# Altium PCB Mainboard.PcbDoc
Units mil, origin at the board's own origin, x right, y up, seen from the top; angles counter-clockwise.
Board outline 3816.81 x 2675.98 mil, 2 copper layers (Top Layer, Bottom Layer); 40 components, 44 nets, 262 pads, 14 vias.
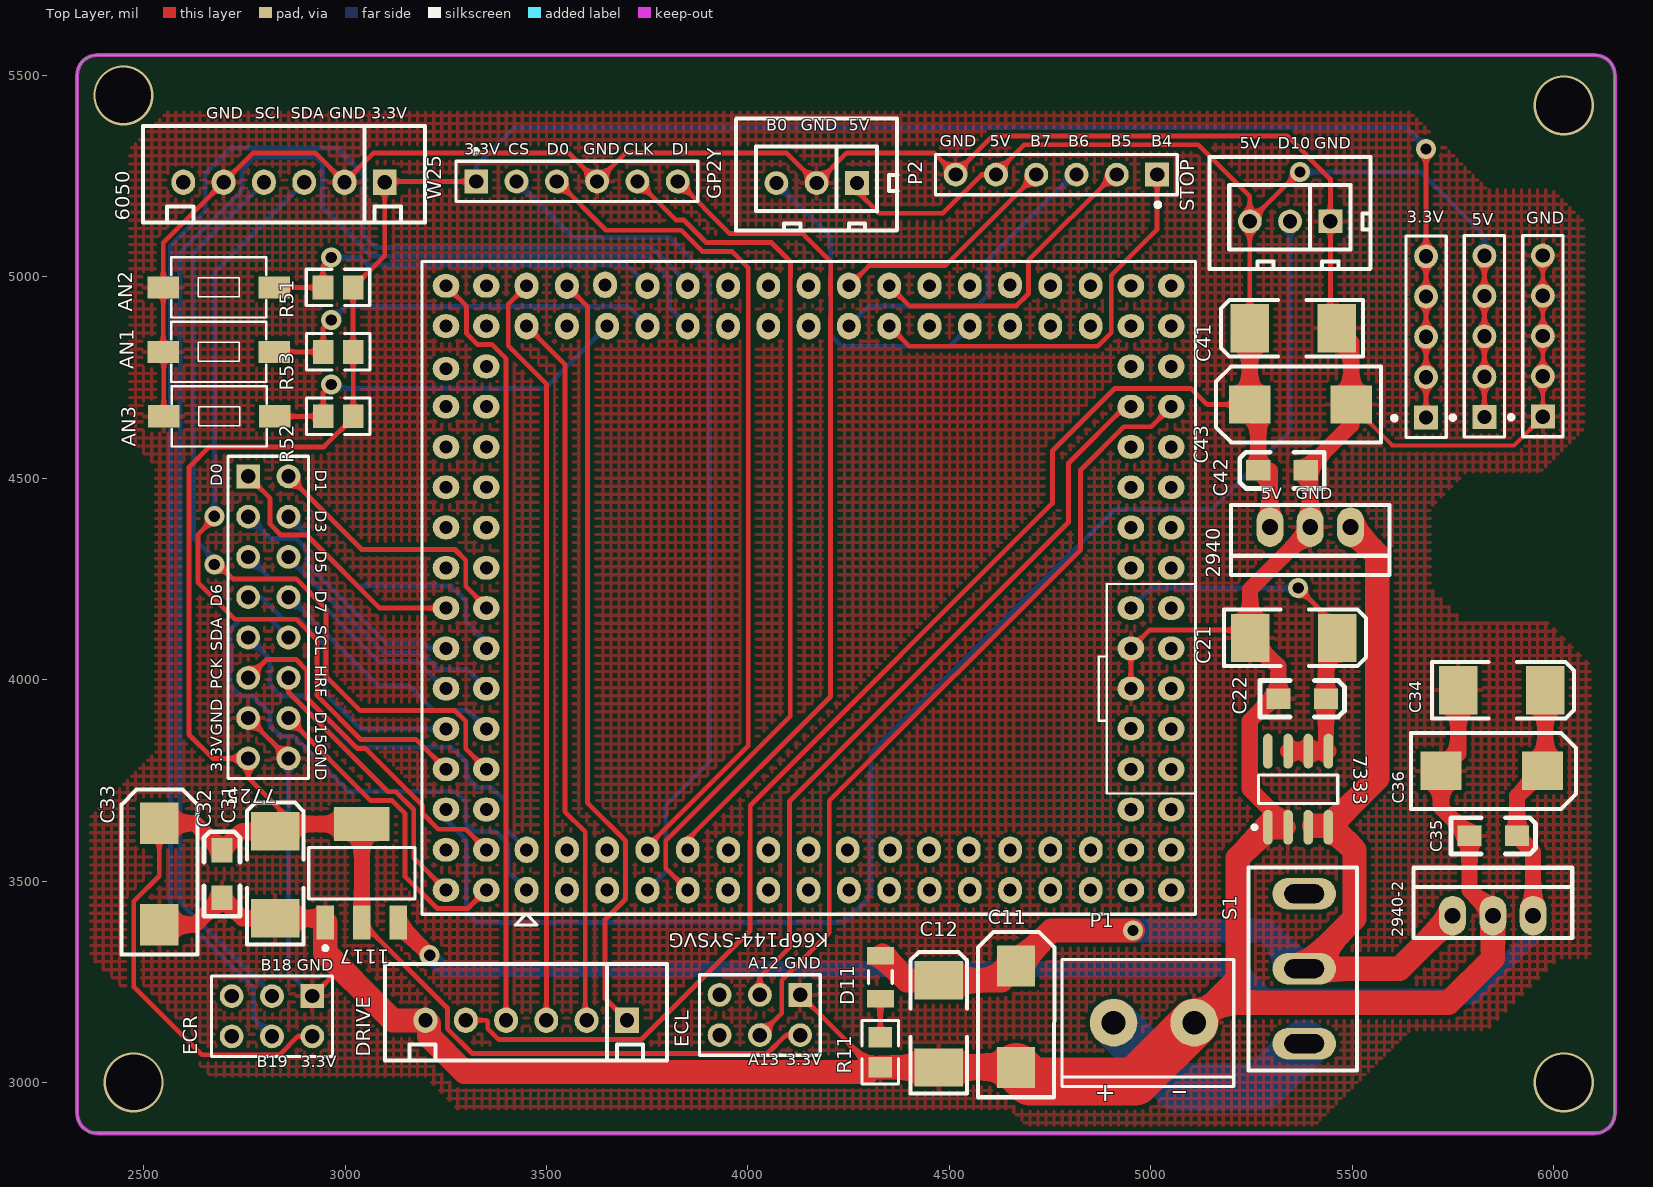
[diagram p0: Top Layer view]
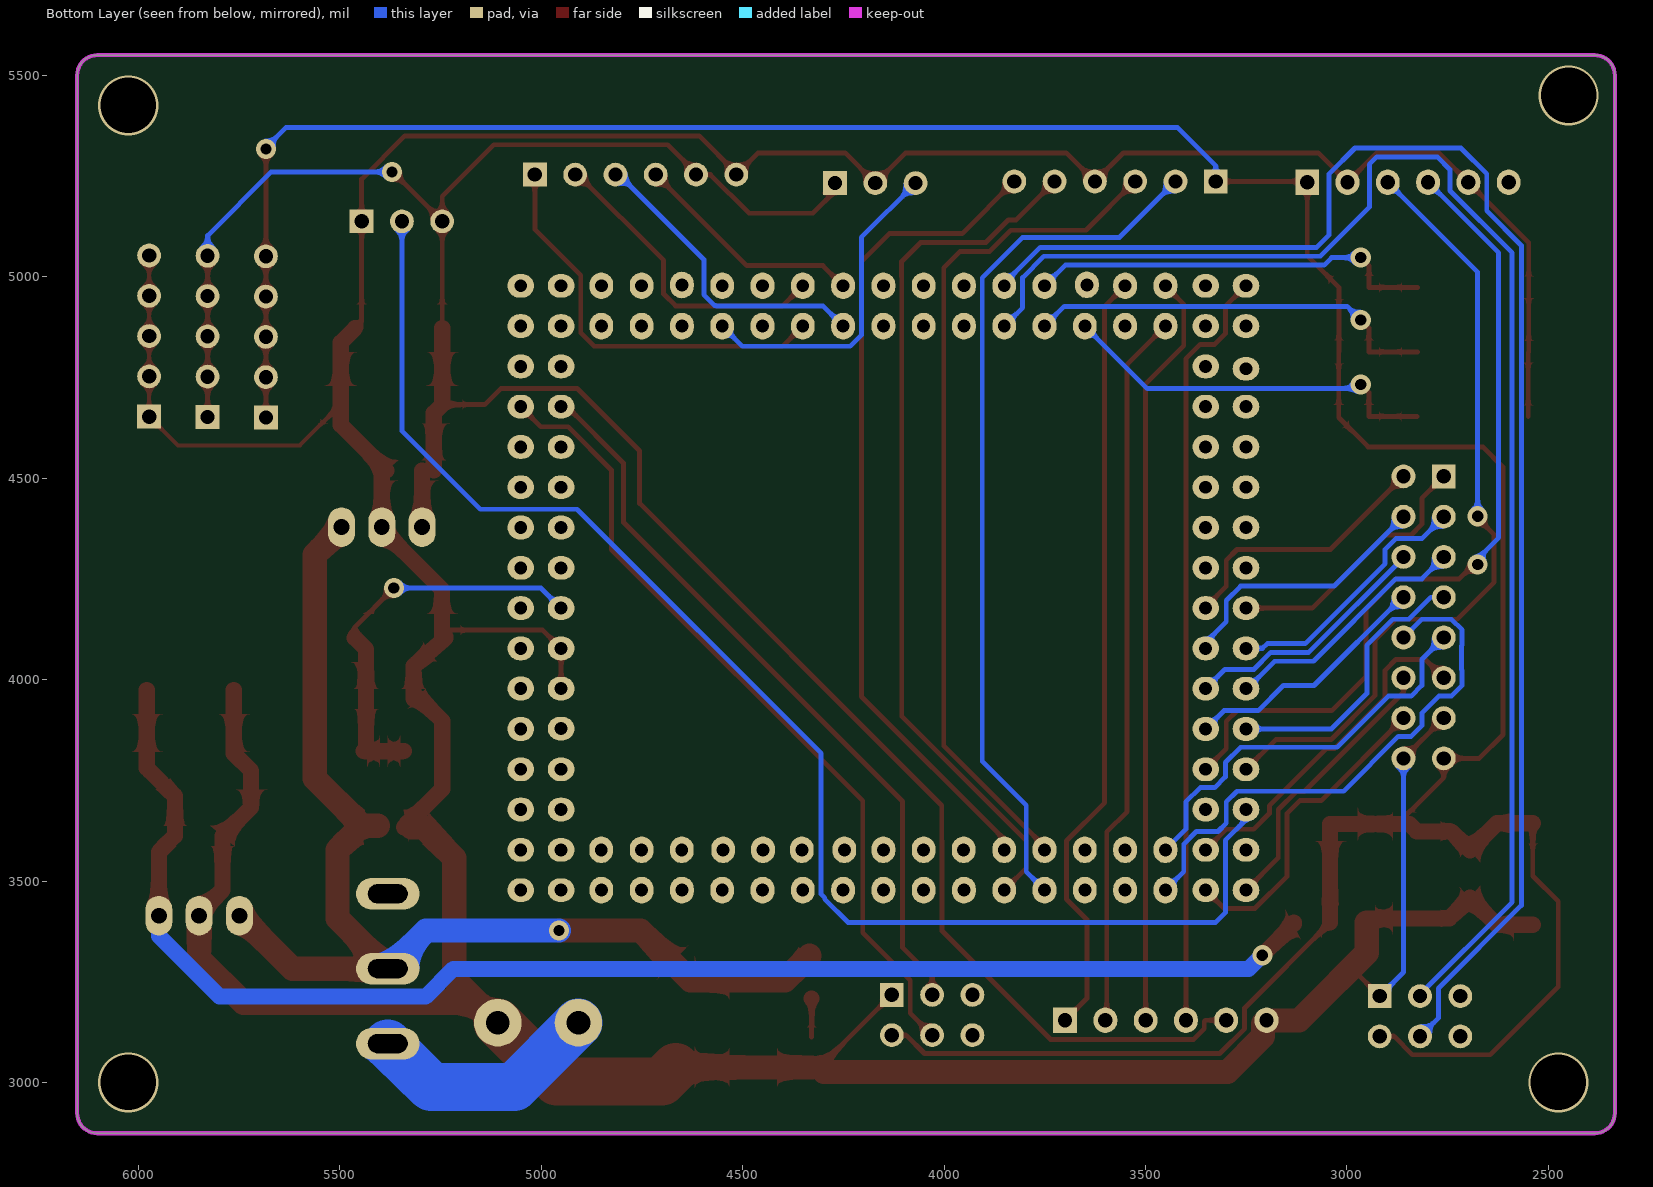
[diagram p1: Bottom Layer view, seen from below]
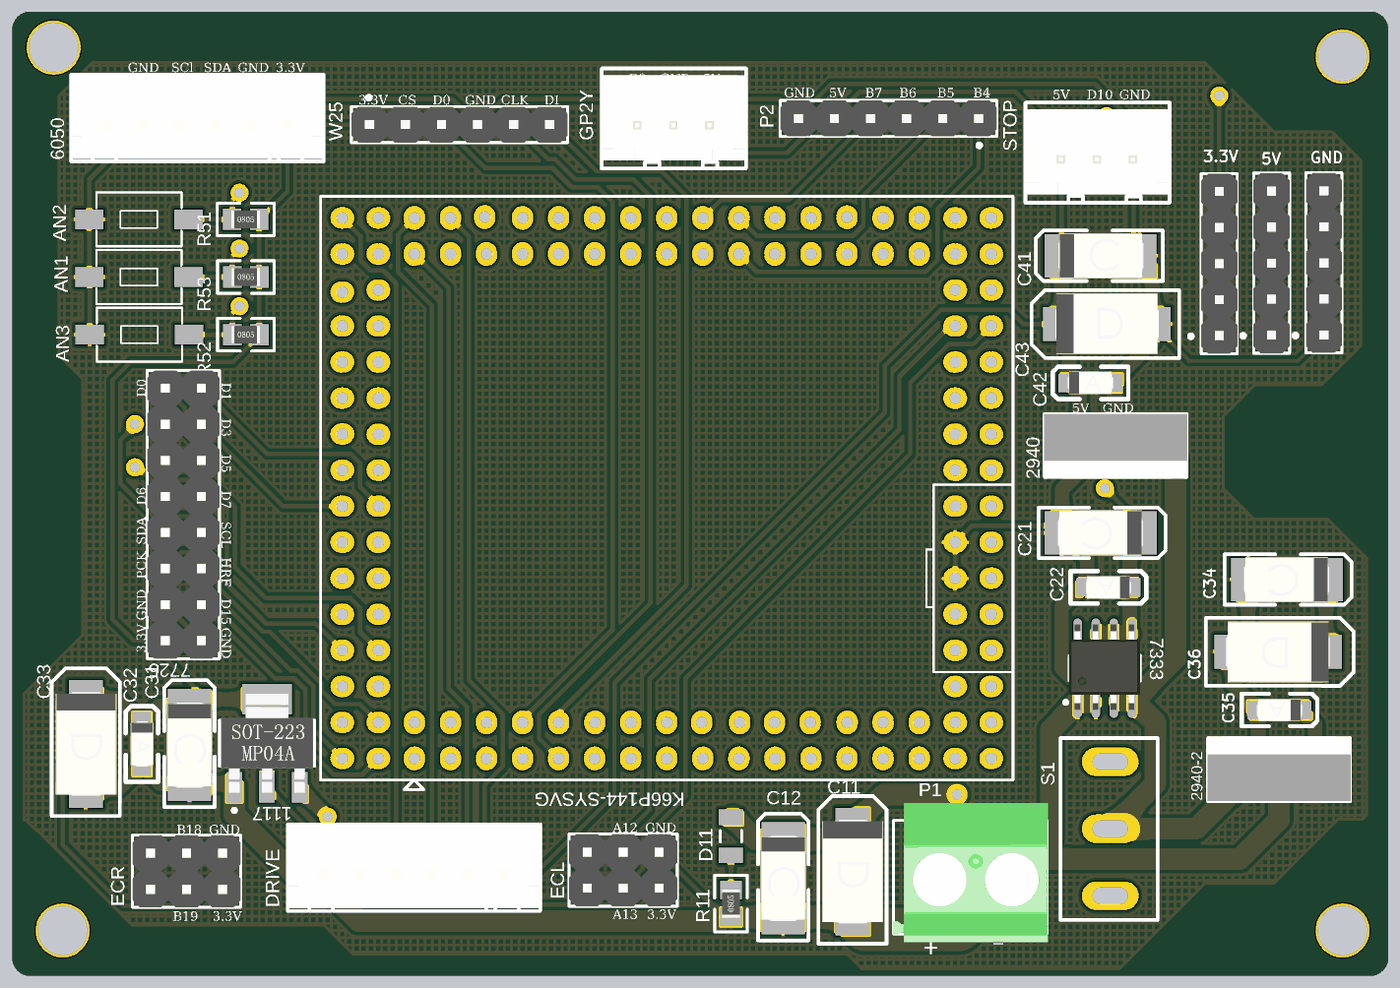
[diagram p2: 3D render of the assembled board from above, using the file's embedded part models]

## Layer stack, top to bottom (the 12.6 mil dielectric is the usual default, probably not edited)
Top Solder: solder mask 0.4, Solder Resist, Dk 3.5
Top Layer: signal copper 1.4
Dielectric 1: dielectric 12.6, FR-4, Dk 4.8
Bottom Layer: signal copper 1.4
Bottom Solder: solder mask 0.4, Solder Resist, Dk 3.5

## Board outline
2385,2874.02 cw(c2385,2924.02) 2335,2924.02 2335,5500 cw(c2385,5500) 2385,5550 6101.81,5550 cw(c6101.81,5500) 6151.81,5500 6151.81,2924.02 cw(c6101.81,2924.02) 6101.81,2874.02

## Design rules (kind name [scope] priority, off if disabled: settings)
Clearance [All] p1: gap=10 ignorepadtopadclearanceinfootprint=FALSE except(0: Arc-Hole Track-Hole SMDPad-Hole THPad-Hole Via-Hole Fill-Hole Poly-Hole Region-Hole Text-Hole)
Height [All] p1: minheight=0 maxheight=2000 prefheight=500
HoleSize [All] p1: absolutevalues=TRUE maxlimit=157.48 minlimit=1 maxpercent=80.000 minpercent=20.000
PolygonConnect [All] p1: connectstyle=Relief reliefconductorwidth=10 reliefentries=4 polygonreliefangle="90 Angle" airgapwidth=10
RoutingVias [All] p1: holewidth=28 width=50 viastyle="Through Hole" minholewidth=28 minwidth=50 maxholewidth=28 maxwidth=50
SilkToSilkClearance [All] p1: silktosilkclearance=0
SilkToSolderMaskClearance [IsPad] p1: minsilkscreentomaskgap=0 clearancetoexposedcopper=TRUE
SolderMaskExpansion [All] p1: expansion=4
Width [All] p1: maxlimit=150 minlimit=10 preferedwidth=12 minimp=50.000000 maximp=50.000000 favimp=50.000000
26 further rules are at their usual default settings.

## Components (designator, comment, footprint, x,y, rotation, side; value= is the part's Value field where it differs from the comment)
3.3V "Header 5" HDR1X5 5683.14,4650.68 r90 top
5V "Header 5" HDR1X5 5828,4652 r90 top
1117 "17" SOT-223 3041.63,3519.44 r0 top
2940 "40-1" TO-220B 5395.63,4378.44 r180 top
2940-2 "LM2940" TO-220B 5849,3414 r0 top
6050 "Header 6" HX2.54-6 3098.63,5234.44 r180 top
7333 "7333" SO8_N 5365.63,3727.95 r90 top
7725 "Header 8X2" HDR2X8 2759.63,4504.44 r270 top
AN1 "Button" SMT4*6*2.5 2686.63,4813.44 r0 top
AN2 "Button" SMT4*6*2.5 2686.63,4973.44 r0 top
AN3 "Button" SMT4*6*2.5 2687.83,4653.44 r0 top
C11 "Cap Pol3" C7343 4665.35,3163.35 r270 top value=100uF
C12 "Cap Pol3" C6032 4472.63,3141.44 r270 top value=10uF
C21 "Cap Pol3" C6032 5350.63,4104.44 r180 top value=10uF
C22 "Cap Pol3" C3216 5375.63,3952.44 r180 top value=0.1uF
C31 "Cap Pol3" C6032 2825.63,3511.44 r270 top value=10uF
C32 "Cap Pol3" C3216 2694.63,3517.44 r270 top value=0.1uF104
C33 "Cap Pol3" C7343 2538.63,3517.44 r270 top value=100uF
C34 "Cap Pol3" C6032 5867,3975 r180 top value=10uF
C35 "Cap Pol3" C3216 5850,3612 r180 top value=0.1uF104
C36 "Cap Pol3" C7343 5846,3774 r180 top value=100uF
C41 "Cap Pol3" C6032 5357.63,4871.44 r0 top value=10uF
C42 "Cap Pol3" C3216 5325.63,4519.44 r0 top value=0.1uF104
C43 "Cap Pol3" C7343 5371.63,4682.44 r0 top value=100uF
D11 "LED1" C1206 4328.63,3261.44 r270 top
DRIVE "Header 6" HX2.54-6 3699.63,3154.44 r180 top
ECL "Header 3X2" HDR2X3 4129.63,3217.44 r180 top
ECR "Header 3X2" HDR2X3 2918.63,3214.44 r180 top
GND "Header 5" HDR1X5 5973.1,4652.68 r90 top
GP2Y "Header 3" HX2.54-3 4270.63,5232.44 r180 top
K66P144-SYSVG "LQ_KXXP144-SYSVG" LQ_KXXP144-SYSVG 3450.63,3477.44 r0 top
P1 "Header 2" 2PIN-5.08A 5107.63,3148.44 r180 top
P2 "Header 6" HDR1X6 5015.63,5253.44 r180 top
R11 "Res3" R0805 4328.63,3074.84 r90 top
R51 "Res3" R0805 2982.63,4973.44 r0 top value=3.3K
R52 "Res3" R0805 2983.03,4653.44 r0 top value=3.3K
R53 "Res3" R0805 2983.03,4813.44 r0 top value=3.3K
S1 "S2W" SW-TO3 5380.63,3282.44 r0 top
STOP "Header 3" HX2.54-3 5445.63,5137.44 r180 top
W25 "MHDR1X6" HDR1X6 3325.63,5236.44 r0 top

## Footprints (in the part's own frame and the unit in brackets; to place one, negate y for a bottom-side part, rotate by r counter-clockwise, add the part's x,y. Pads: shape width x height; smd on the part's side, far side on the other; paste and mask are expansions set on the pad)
2PIN-5.08A [mm]
  round 3 hole 1.5: 1(0,0) 2(5.08,0)
  silkscreen extent -2.49,-3.99 8.33,4.01, body extent -2.54,-5.2 8.36,4.6, height 14.2
C1206 [mm] "Chip Capacitor, Body 3.2x1.6mm, IPC High Density"
  rect 1.1x1.7 smd: 1(-1.35,0) 2(1.35,0)
  silkscreen extent -0.4,-0.75 0.4,0.75, body extent -1.7,-0.9 1.7,0.9, height 1.3
C3216 [mil] "A型/1206"
  rect 60x51.18 smd: 1(-59,0) 2(59,0)
  silkscreen extent -105,-45 105,45, body extent -63,-31 63,32, height 63
C6032 [mil] "C型"
  rect 95x120 smd: 1(-112,1) 2(104,1)
  silkscreen extent -183,-69 169,71, body extent -121,-62 115,64, height 102
C7343 [mm] "D型"
  rect 2.6x2.4 smd: 1(-3.202,0.007) 2(3.198,0.007)
  silkscreen extent -5.33,-2.39 5.08,2.41, body extent -3.65,-2.12 3.65,2.18, height 2.9
HDR1X5 [mm] "Connector; Header; 5 Position"
  rect 1.5x1.5 hole 0.9: 1(0,0)
  round 1.5 hole 0.9: 2(2.54,0) 3(5.08,0) 4(7.62,0) 5(10.16,0)
  silkscreen extent -1.27,-1.27 11.43,2.14, body extent -1.27,-1.27 11.43,1.27, height 8.54
HDR1X6 [mm] "Connector; Header; 6 Position"
  rect 1.5x1.5 hole 0.9: 1(0,0)
  round 1.5 hole 0.9: 2(2.54,0) 3(5.08,0) 4(7.62,0) 5(10.16,0) 6(12.7,0)
  silkscreen extent -1.27,-1.27 13.97,2.04, body extent -1.27,-1.27 13.97,1.27, height 8.54
HDR2X3 [mm] "Connector; Header; 3x2 Position"
  rect 1.5x1.5 hole 0.9: 1(0,0)
  round 1.5 hole 0.9: 2(0,2.54) 3(2.54,0) 4(2.54,2.54) 5(5.08,0) 6(5.08,2.54)
  silkscreen extent -1.27,-1.27 6.35,3.81, body extent -1.27,-1.27 6.35,3.81, height 8.54
HDR2X8 [mm] "Connector; Header; 8x2 Position"
  rect 1.5x1.5 hole 0.9: 1(0,0)
  round 1.5 hole 0.9: 2(0,2.54) 3(2.54,0) 4(2.54,2.54) 5(5.08,0) 6(5.08,2.54) 7(7.62,0) 8(7.62,2.54) 9(10.16,0) 10(10.16,2.54) 11(12.7,0) 12(12.7,2.54) 13(15.24,0) 14(15.24,2.54) 15(17.78,0) 16(17.78,2.54)
  silkscreen extent -1.27,-1.27 19.05,3.81, body extent -1.27,-1.27 19.05,3.81, height 8.54
HX2.54-3 [mm]
  rect 1.5x1.5 hole 0.9: 1(0,0)
  round 1.5 hole 0.9: 2(2.54,0) 3(5.08,0)
  silkscreen extent -2.54,-4.06 7.63,3, body extent -2.41,-3.58 7.59,2.42, height 7
HX2.54-6 [mm]
  rect 1.5x1.6 hole 0.9: 1(0,0)
  oval 1.5x1.6 hole 0.9: 2(2.54,0) 3(5.08,0) 4(7.62,0) 5(10.16,0) 6(12.7,0)
  silkscreen extent -2.54,-3.56 15.24,2.54, body extent -2.54,-3.63 15.24,2.36, height 6.1
LQ_KXXP144-SYSVG [mil]
  oval 59x66 hole 32: 1(0,0) 2(0,100) 3(100,0) 4(100,100) 5(200,0) 6(200,100) 7(300,0) 8(300,100) 9(400,0) 10(400,100) 11(500,0) 12(500.79,100) 13(600,0) 14(600,100) 15(700,0) 16(700,100) 17(800,0) 18(796.85,100) 19(900,0) 20(902.36,100) 21(1000,0) 22(998.82,100) 23(1100,0) 24(1097.64,100) 25(1200,0) 26(1200.39,100) 27(1300,0) 28(1300,100) 29(1400,0) 30(1400.39,100) 63(1400,1500) 64(1400,1400) 65(1300,1500) 66(1300,1400) 67(1200,1501.97) 68(1200,1400) 69(1100,1500) 70(1100,1400) 71(1000,1500) 72(1000,1400) 73(900,1500) 74(900,1400) 75(800,1500) 76(800,1400) 77(700,1500) 78(700,1400) 79(600,1500) 80(600,1400) 81(500,1500) 82(500,1400) 83(400,1500) 84(400,1400) 85(300,1500) 86(300,1400) 87(194.88,1502.36) 88(200,1400) 89(100,1500) 90(100,1400) 91(0,1500) 92(0,1400)
  oval 66x59 hole 32: 31(1500,0) 32(1600,0) 33(1500,100) 34(1600,100) 35(1500,200) 36(1600,200) 37(1500,300) 38(1600,300) 39(1500,400.79) 40(1600,400) 41(1500,500) 42(1600,500.39) 43(1500,600) 44(1600,600) 45(1500,700) 46(1600,700) 47(1500,800) 48(1600,800) 49(1500,900) 50(1600,900) 51(1500,1000) 52(1600,1000) 53(1500,1100) 54(1600,1100) 55(1500,1200) 56(1600,1200) 57(1500,1300) 58(1600,1300) 59(1500,1400) 60(1600,1400) 61(1500,1500) 62(1600,1500) 93(-100,1500) 94(-200,1500) 95(-100,1400) 96(-200,1400) 97(-100,1300) 98(-200,1294.09) 99(-100,1200) 100(-200,1200) 101(-100,1100) 102(-200,1100) 103(-100,1000) 104(-200,1000) 105(-100,899.61) 106(-200,900.39) 107(-100,800) 108(-200,800) 109(-100,700) 110(-200,700) 111(-100,600) 112(-200,600) 113(-100,500) 114(-200,500) 115(-100,400) 116(-200,400) 117(-100,300) 118(-200,300) 119(-100,200) 120(-200,200) 121(-100,100) 122(-200,100) 123(-100,0) 124(-200,0)
  silkscreen extent -260,-87 1660,1560
R0805 [mm]
  rect 1.3x1.5 smd: 1(-0.95,0) 2(0.95,0)
  silkscreen extent -2,-1.15 2,1.15, body extent -1,-0.63 1,0.63, height 0.55
SMT4*6*2.5 [mm]
  rect 2x1.4 smd: 1(-3.5,0) 2(3.5,0)
  silkscreen extent -3,-1.9 3,1.9, body extent -2.85,-1.75 3.25,1.95, height 2.5
SO8_N [mm] "SOIC, 8-Leads, Body 4.9x3.9mm, Pitch 1.27mm, IPC Medium Density"
  oval 2.2x0.6 smd: 1(-2.4,1.905) 2(-2.4,0.635) 3(-2.4,-0.635) 4(-2.4,-1.905) 5(2.4,-1.905) 6(2.4,-0.635) 7(2.4,0.635) 8(2.4,1.905)
  silkscreen extent -2.52,-2.5 0.9,2.88, body extent -2.94,-2.48 3.1,2.54, height 1.6
SOT-223 [mm]
  rect 1.1x2.15 smd: 1(-2.3,-3.1) 2(0,-3.1) 3(2.3,-3.1)
  rect 3.5x2.15 smd: 2(0,3.1)
  silkscreen extent -3.35,-4.85 3.35,1.63, body extent -3.25,-3.48 3.25,3.48, height 1.7
SW-TO3 [mm]
  oval 4x2 hole 1.2 slot 2.5 at 0 deg: 1(0,-4.724) 2(0,0) 3(0,4.724)
  silkscreen extent -3.5,-6.43 3.33,6.39, body extent -3.43,-6.36 3.43,6.35, height 28.55
TO-220B [mm]
  oval 1.7x2.5 hole 1: 1(-2.54,0) 2(0,0) 3(2.54,0)
  silkscreen extent -5,-1.4 5,3.02, body extent -5.08,-1.4 5.08,3.18, height 18.54

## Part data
3.3V 5V GND: "Header, 5-Pin"
1117: library part AMS1117, "SOT-223"
2940: library part LM2940, "SOT-223"
2940-2: "SOT-223"
6050 DRIVE P2 W25: "Header, 6-Pin"
7725: "Header, 8-Pin, Dual row"
C11 C12 C21 C22 C31 C32 C33 C34 C35 C36 C41 C42 C43: "Polarized Capacitor (Surface Mount)"
D11: library part LED3, "Typical BLUE SiC LED"
ECL ECR: "Header, 3-Pin, Dual row"
GP2Y STOP: "Header, 3-Pin"
P1: "Header, 2-Pin"
R11 R51 R52 R53: "Resistor"
S1: library part SW-SPST, "Single-Pole, Single-Throw Switch"

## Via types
v1: diameter 50, hole 28, Top Layer to Bottom Layer, 10 vias
v2: diameter 149.61, hole 137.8, Top Layer to Bottom Layer, 4 vias

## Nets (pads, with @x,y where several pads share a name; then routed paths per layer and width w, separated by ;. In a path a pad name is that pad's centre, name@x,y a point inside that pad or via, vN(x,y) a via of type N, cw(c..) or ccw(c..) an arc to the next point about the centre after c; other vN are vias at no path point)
3.3V: 3.3V.1 3.3V.2 3.3V.3 3.3V.4 3.3V.5 1117.2 6050.1 7725.15 C31.1 C32.1 C33.1 ECL.2 ECR.2 R51.2 R52.2 R53.2 W25.1 | length 8501.5
  Top Layer w12: C33.1 2538.91,3512.59 2475.66,3449.34 2475.66,3237.41 2644.16,3068.91 2837.49,3068.91 2883.02,3114.44 ECR.2 ; C31.1@2866.63,3649.49 2759.63,3756.49 7725.15 2671.63,3804.44 2612.63,3863.44 2612.63,4527.44 2662.63,4577.44 2947.38,4577.44 3020.43,4650.5 R52.2 R53.2 3020.03,4813.84 R51.2 3098.63,5052.04 6050.1 3100.63,5236.44 W25.1 ; 1117.2@3041.63,3397.39 3254.1,3184.92 3254.1,3133.61 3315.8,3071.91 4048.49,3071.91 4094.02,3117.44 ECL.2 ; v1(5683,5317) 5683,5106.82 5683.14,5106.68 3.3V.5 3.3V.4 3.3V.3 3.3V.2 3.3V.1
  Top Layer w40: C33.1 2627.57,3643.5 C32.1 2741.63,3623.44 C31.1 2844.68,3641.49 3041.63,3641.49 1117.2@3041.63,3397.39
  Bottom Layer w12: W25.1 3325.63,5275.63 3420,5370 5634,5370 5683,5321 v1(5683,5317)
5V: 5V.1 5V.2 5V.3 5V.4 5V.5 2940.3 C41.1 C42.1 C43.1 DRIVE.5 GP2Y.1 P2.5 STOP.3 | length 6078.9
  Top Layer w12: DRIVE.5 3351.84,3154.44 3354.1,3152.18 3354.1,3133.61 3380.77,3106.94 3735.78,3106.94 4005.13,3376.29 4005.13,3599.79 4005.63,3600.29 4005.63,3687.44 4755.63,4437.44 4755.63,4567.44 4911.13,4722.94 5099.63,4722.94 5139.85,4682.72 C43.1 ; GP2Y.1@4295.63,5207.44 GP2Y.1 4270.63,5212.44 4325.63,5157.44 4484.02,5157.44 4580.02,5253.44 P2.5 4615.63,5257.44 4685.63,5327.44 5117.63,5327.44 5245.63,5199.44 STOP.3 ; C41.1 C41.1 STOP.3 ; v1(5370,5260) 5368.19,5260 STOP.3 ; 5V.1 5V.2 5V.3 5V.4 5V.5
  Top Layer w40: C41.1 C43.1 5266.63,4661.65 C42.1 ; 2940.3 C42.1@5295.63,4519.44
  Bottom Layer w12: v1(5370,5260) 5670,5260 ; 5671,5260 5670,5260 ; 5V.5 5828,5102 5670,5260
5V-2: 1117.3 2940-2.3 C34.1 C35.1 C36.1 | length 3613.3
  Top Layer w40: 1117.3 3132.18,3393.82 v1(3210,3316) ; 2940-2.3 5949,3572 C35.1 5909,3710.66 C36.1 5979,3780.66 C34.1
  Bottom Layer w40: v1(3210,3316) 3244,3282 5218,3282 5286.93,3213.07 5798.07,3213.07 5949,3364 2940-2.3
ADC1_SE8: GP2Y.3 K66P144-SYSVG.70 | length 810.7
  Bottom Layer w12: GP2Y.3 4205.13,5097.94 4205.13,4855.09 4232.78,4827.44 4500.63,4827.44 K66P144-SYSVG.70
ADC1_SE10: K66P144-SYSVG.74 P2.1 | length 1025.5
  Top Layer w12: K66P144-SYSVG.74 4400.63,4827.44 4868.48,4827.44 4901.63,4860.59 4901.63,5003.44 5015.63,5117.44 P2.1
ADC1_SE11: K66P144-SYSVG.73 P2.2 | length 769.8
  Top Layer w12: K66P144-SYSVG.73 4400.63,4927.44 4666.51,4927.44 4696.13,4957.06 4696.13,5040.79 4908.78,5253.44 P2.2
ADC1_SE12: K66P144-SYSVG.76 P2.3 | length 772.1
  Bottom Layer w12: K66P144-SYSVG.76 4300.63,4927.44 4565.63,4927.44 4566.63,4928.44 4569.48,4928.44 4596.13,4955.09 4596.13,5042.76 4806.82,5253.44 P2.3
ADC1_SE13: K66P144-SYSVG.75 P2.4 | length 579.3
  Top Layer w12: K66P144-SYSVG.75 4300.63,5027.44 4489.63,5027.44 P2.4
CLK: K66P144-SYSVG.9 W25.5 | length 2173.2
  Top Layer w12: W25.5 3821.16,5140.91 3840.04,5140.91 3896.02,5084.94 4058.13,5084.94 4105.63,5037.44 4105.63,5000.29 4105.13,4999.79 4105.13,3908.79 3796.13,3599.79 3796.13,3531.94 K66P144-SYSVG.9
CS: K66P144-SYSVG.7 W25.2 | length 2162.5
  Bottom Layer w12: W25.2 3564.63,5097.44 3805.13,5097.44 3905.13,4997.44 3905.13,3796.94 3796.13,3687.94 3796.13,3522.94 K66P144-SYSVG.7
D0: 7725.1 K66P144-SYSVG.110 | length 667.2
  Top Layer w12: 7725.1 2814.1,4449.97 2814.1,4385.58 2840.77,4358.91 2905.16,4358.91 3086.63,4177.44 K66P144-SYSVG.110 K66P144-SYSVG.110@3250.63,4180.44
D1: 7725.2 K66P144-SYSVG.109 | length 666.2
  Top Layer w12: 7725.2 3041.13,4322.94 3272.98,4322.94 3299.63,4296.29 3299.63,4231.44 3350.63,4180.44 K66P144-SYSVG.109
D2: 7725.3 K66P144-SYSVG.112 | length 647.1
  Bottom Layer w12: 7725.3 2814.1,4349.97 2878.49,4349.97 2905.16,4323.3 2905.16,4288.07 3103.78,4089.44 3197.86,4089.44 3209.86,4077.44 K66P144-SYSVG.112
D3: 7725.4 K66P144-SYSVG.111 | length 666.2
  Bottom Layer w12: 7725.4 3032.13,4231.94 3263.98,4231.94 3299.63,4196.29 3299.63,4143.44 3350.63,4092.44 K66P144-SYSVG.111
D4: 7725.5 K66P144-SYSVG.114 | length 626.4
  Bottom Layer w12: 7725.5 2814.1,4249.97 2878.49,4249.97 3083.02,4045.44 3179.63,4045.44 3247.63,3977.44 K66P144-SYSVG.114
D5: 7725.6 K66P144-SYSVG.113 | length 627.6
  Bottom Layer w12: 7725.6 2859.63,4302.48 3094.67,4067.44 3188.74,4067.44 3230.76,4025.42 3302.65,4025.42 K66P144-SYSVG.113
D6: 7725.7 K66P144-SYSVG.116 | length 696.7
  Bottom Layer w12: 7725.7 2791.63,4204.44 2846.1,4149.97 2886.1,4149.97 2950.63,4085.44 2950.63,3965.44 3038.63,3877.44 K66P144-SYSVG.116
D7: 7725.8 K66P144-SYSVG.115 | length 626.4
  Bottom Layer w12: 7725.8 2862.74,4204.44 3081.74,3985.44 3157.63,3985.44 3220.13,3922.94 3305.13,3922.94 K66P144-SYSVG.115
DI: K66P144-SYSVG.10 W25.6 | length 2069.9
  Top Layer w12: W25.6 3955.13,5106.94 4136.13,5106.94 4205.63,5037.44 4205.63,5000.29 4205.13,4999.79 4205.13,4955.09 4205.63,4954.59 4205.63,4900.29 4205.13,4899.79 4205.13,3958.05 3850.63,3603.55 K66P144-SYSVG.10
DO: K66P144-SYSVG.8 W25.3 | length 2112.2
  Top Layer w12: W25.3 3526.63,5236.44 3647.63,5115.44 3834.4,5115.44 3886.9,5062.94 3960.13,5062.94 4000.63,5022.44 4000.63,3835.4 3750.63,3585.4 K66P144-SYSVG.8
"ECL A12": ECL.3 K66P144-SYSVG.55 | length 1850.3
  Top Layer w12: ECL.3 4029.63,3261.44 4102.78,3334.59 4102.78,3697.44 4795.63,4390.29 4795.63,4537.44 4935.63,4677.44 K66P144-SYSVG.55
"ECL A13": ECL.4 K66P144-SYSVG.56 | length 2022.7
  Top Layer w12: ECL.4 4084.1,3171.91 4084.1,3253.6 4201.98,3371.47 4201.98,3698.79 4825.63,4322.44 4825.63,4520.29 4932.78,4627.44 5000.63,4627.44 K66P144-SYSVG.56
"ECR B18": ECR.3 K66P144-SYSVG.84 | length 3609.8
  Bottom Layer w12: ECR.3 2818.63,3218.88 2590,3447.51 2590,5059.46 2744.16,5213.61 2744.16,5265.97 2775.63,5297.44 2925.63,5297.44 2944.16,5278.91 2944.16,5172.56 3065.91,5050.8 3752.27,5050.8 3805.13,4997.94 3805.13,4922.94 K66P144-SYSVG.84
"ECR B19": ECR.4 K66P144-SYSVG.83 | length 3738.9
  Bottom Layer w12: ECR.4 2773.1,3159.97 2773.1,3233.3 2567,3439.4 2567,5077.51 2653.1,5163.61 2653.1,5255.27 2717.28,5319.44 2979.98,5319.44 3044.16,5255.27 3044.16,5103.67 3075.03,5072.8 3761.38,5072.8 3850.63,4983.55 K66P144-SYSVG.83
GND: 1117.1 2940-2.2 2940.2 6050.2 6050.5 7333.1 7333.2 7725.13 7725.16 AN1.1 AN2.1 AN3.1 C11.2 C12.2 C21.2 C22.2 C31.2 C32.2 C33.2 C34.2 C35.2 C36.2 C41.2 C42.2 C43.2 DRIVE.6 ECL.1 ECR.1 GND.1 GND.2 GND.3 GND.4 GND.5 GP2Y.2 K66P144-SYSVG.41 K66P144-SYSVG.43 P1.1 P2.6 R11.1 STOP.1 W25.4 | length 13029.5
  Top Layer w10: C43.2 5599.25,4581 ; 5598.25,4581 5599.25,4581 ; 5900.43,4581 5599.25,4581 ; 5901.43,4581 GND.1 GND.2 GND.3 GND.4 GND.5
  Top Layer w12: AN3.1 2550.04,4812.24 AN1.1 AN2.1 2548.83,5084.65 6050.5 2771.63,5307.44 2925.63,5307.44 6050.2 3071.63,5307.44 3554.63,5307.44 W25.4 3696.63,5307.44 4095.63,5307.44 GP2Y.2 4245.63,5307.44 4461.63,5307.44 P2.6 4515.63,5257.44 4607.63,5349.44 5338.54,5349.44 5445.63,5242.35 STOP.1 5445.63,4888.44 C41.2 ; 7725.13 7725.16 ; ECR.1 2986.63,3282.44 2990.63,3282.44 ; 1117.1 1117.1@2951.08,3412.89 ; 3052.63,3214.44 3055.63,3217.44 ; ECL.1 4309.63,3037.44 R11.1 ; K66P144-SYSVG.41 K66P144-SYSVG.43 4996.13,4122.94 5227.13,4122.94 C21.2@5237.63,4103.44
  Top Layer w40: C33.2 2627.72,3391.54 C32.2 2745.63,3407.44 C31.2 2941.03,3407.44 1117.1 ; C21.2@5237.63,4103.44 5242.67,4098.97 5316.63,4033.44 C22.2 5300.63,3952.44 5245.63,3897.44 5245.63,3728.46 7333.2 ; C21.2 5246.63,4223.94 5395.63,4372.94 2940.2 C42.2@5395.63,4501.44 ; C42.2 5497.54,4632.35 C43.2 5497.54,4836.54 C41.2 ; C34.2 5763,3816.63 C36.2 5720.09,3682.91 C35.2 5791,3477.5 5849,3419.5 2940-2.2
  Top Layer w60: 1117.1 2951.08,3321.99 2990.63,3282.44 3055.63,3217.44 3118.93,3154.15 3199.63,3154.15 3208.1,3145.67 3208.1,3114.56 3296.75,3025.91 4298.1,3025.91 R11.1@4309.63,3037.44 ; R11.1 C12.2 C11.2 ; P1.1 5157.19,3198 ; 7333.1@5290.63,3632.44 5215.63,3557.44 5215.63,3256.44 5157.19,3198 ; 7333.1 5321.65,3633.46 5325.63,3637.44 ; 2940-2.2 5849,3308 5739,3198 5157.19,3198
  Top Layer w120: C11.2 4700.63,3002.44 4961.63,3002.44 P1.1
  Bottom Layer w12: 7725.16 2859.63,3273.44 ECR.1
HRF: 7725.12 K66P144-SYSVG.124 | length 700.5
  Top Layer w12: 7725.12 2859.63,3968.83 3106.65,3721.81 3126.27,3721.81 3170.53,3677.55 3170.53,3557.54 K66P144-SYSVG.124
IIC_SCL: 6050.4 K66P144-SYSVG.117 | length 2066.2
  Top Layer w12: v1(2675.63,4285.44) 2685.63,4285.44 2721.1,4249.97 2878.49,4249.97 2952.63,4175.83 2952.63,4008.44 3038.13,3922.94 3272.98,3922.94 3299.63,3896.29 3299.63,3828.44 K66P144-SYSVG.117
  Bottom Layer w12: v1(2675.63,4285.44) 2675.63,4300.44 2623.63,4352.44 2623.63,5059.44 6050.4
IIC_SDA: 6050.3 K66P144-SYSVG.118 | length 1991.3
  Top Layer w12: v1(2675.63,4405.44) 2675.63,4400.44 2634.63,4359.44 2634.63,4241.44 2726.1,4149.97 2878.49,4149.97 2930.63,4097.83 2930.63,3960.05 3039.53,3851.15 3176.92,3851.15 K66P144-SYSVG.118
  Bottom Layer w12: v1(2675.63,4405.44) 2675.63,5011.44 6050.3
KEY1: AN1.2 K66P144-SYSVG.86 R53.1 | length 1027.9
  Top Layer w12: AN1.2 R53.1 2945.63,4872.44 v1(2965.63,4892.44)
  Bottom Layer w12: v1(2965.63,4892.44) 2999.63,4926.44 3701.63,4926.44 K66P144-SYSVG.86
KEY2: AN2.2 K66P144-SYSVG.85 R51.1 | length 1017.2
  Top Layer w12: AN2.2 R51.1 2945.23,5027.04 v1(2965.63,5047.44)
  Bottom Layer w12: v1(2965.63,5047.44) 3038.16,5047.44 3056.8,5028.8 3699.27,5028.8 K66P144-SYSVG.85
KEY3: AN3.2 K66P144-SYSVG.88 R52.1 | length 963.4
  Top Layer w12: AN3.2 R52.1 2945.63,4712.44 v1(2965.63,4732.44)
  Bottom Layer w12: v1(2965.63,4732.44) 2965.63,4728.44 2971.13,4722.94 3272.98,4722.94 3273.48,4722.44 3327.78,4722.44 3328.28,4722.94 3372.98,4722.94 3373.48,4722.44 3495.63,4722.44 K66P144-SYSVG.88
NetD11_2: D11.2 R11.2 | length 96
  Top Layer w12: R11.2 D11.2
NetP1_2: P1.2 S1.1 | length 583.6
  Bottom Layer w120: P1.2 5067.13,2988.94 5273.13,2988.94 S1.1
PCK: 7725.11 K66P144-SYSVG.121 | length 857
  Top Layer w12: 7725.11 2805.16,4049.97 2878.49,4049.97 2905.16,4023.3 2905.16,3954.41 3030.42,3829.15 3050.04,3829.15 3192.53,3686.66 3192.53,3667.7 3231.78,3628.44 3299.63,3628.44 K66P144-SYSVG.121
PWM1: DRIVE.1 K66P144-SYSVG.89 | length 1926.6
  Top Layer w12: K66P144-SYSVG.89 3601.63,4926.44 3601.63,3694.29 3696.13,3599.79 3696.13,3455.09 3645.63,3404.59 3645.63,3208.44 DRIVE.1
PWM2: DRIVE.2 K66P144-SYSVG.92 | length 1784.7
  Top Layer w12: K66P144-SYSVG.92 3545.63,4782.44 3545.63,3672.4 3596.13,3621.9 3596.13,3157.94 DRIVE.2
PWM3: DRIVE.3 K66P144-SYSVG.91 | length 1881
  Top Layer w12: K66P144-SYSVG.91 3405.13,4931.94 3405.13,4828.44 3499.63,4733.94 DRIVE.3
PWM4: DRIVE.4 K66P144-SYSVG.94 | length 1905.6
  Top Layer w12: K66P144-SYSVG.94 3301.63,4926.44 3301.63,4858.59 3328.28,4831.94 3363.98,4831.94 3399.63,4796.29 DRIVE.4
SCCBSCL: 7725.10 K66P144-SYSVG.1 | length 1351.1
  Bottom Layer w12: 7725.10 2814.1,4149.97 2740.77,4149.97 2714.1,4123.3 2714.1,4085.58 2715.63,4084.06 2715.63,4024.83 2714.1,4023.3 2714.1,3985.58 2740.77,3958.91 2772.16,3958.91 2814.1,3916.97 2814.1,3885.58 2840.77,3858.91 2872.16,3858.91 3008.13,3722.94 3272.98,3722.94 3299.63,3696.29 3299.63,3643.44 3320.13,3622.94 3374.02,3622.94 3405.13,3591.83 3405.13,3522.94 K66P144-SYSVG.1
SCCBSDA: 7725.9 K66P144-SYSVG.2 | length 1007.7
  Bottom Layer w12: 7725.9 2814.1,4049.97 2814.1,3985.58 2840.77,3958.91 2897.16,3958.91 3024.13,3831.94 3263.98,3831.94 3301.63,3794.29 3301.63,3758.59 3328.28,3731.94 3363.98,3731.94 3399.63,3696.29 3399.63,3628.44 K66P144-SYSVG.2
STOP: K66P144-SYSVG.120 STOP.2 | length 3563.1
  Bottom Layer w12: K66P144-SYSVG.120 3250.63,3652.44 3301.63,3601.44 3301.63,3421.44 3325.63,3397.44 4238.48,3397.44 4296.13,3455.09 4296.13,3458.44 4305.13,3467.44 4305.13,3816.94 4911.13,4422.94 5151.13,4422.94 5345.63,4617.44 STOP.2
VB: 2940-2.1 2940.1 7333.3 7333.4 C11.1 C12.1 D11.1 S1.2 | length 2887.6
  Top Layer w40: D11.1 D11.1@4334.02,3314.59
  Top Layer w60: D11.1@4334.02,3314.59 4395.17,3253.44 C12.1 4629.66,3253.44 C11.1 4753.66,3377.44 v1(4955.63,3377.44) ; 5405.63,3637.44 7333.4@5444.61,3637.44 ; 2940.1 5495.63,4376.44 5562,4310.07 5562,3754.83 7333.4@5444.61,3637.44 ; 2940-2.1 5617.44,3282.44 S1.2 5505.63,3407.44 5505.63,3577.44 5449.61,3633.46 7333.4 7333.4@5444.61,3637.44
  Bottom Layer w60: v1(4955.63,3377.44) 5285.63,3377.44 S1.2
VCC: 7333.5 7333.6 7333.7 C21.1 C22.1 K66P144-SYSVG.45 | length 995
  Top Layer w12: v1(5365.63,4227.44) 5462.63,4130.44 C21.1
  Top Layer w40: 7333.7 7333.6 7333.5 5434.63,3828.44 C22.1 5434.63,4075.44 C21.1
  Bottom Layer w12: K66P144-SYSVG.45 5000.63,4227.44 v1(5365.63,4227.44)
VSY: 7725.14 K66P144-SYSVG.123 | length 797.4
  Top Layer w12: 7725.14 3064.26,3699.81 3117.16,3699.81 3148.53,3668.44 3148.53,3511.7 3228.28,3431.94 3305.13,3431.94 K66P144-SYSVG.123
pads on no net: 6050.6 7333.8 ECL.5 ECL.6 ECR.5 ECR.6 K66P144-SYSVG.3 K66P144-SYSVG.4 K66P144-SYSVG.5 K66P144-SYSVG.6 K66P144-SYSVG.11 K66P144-SYSVG.12 K66P144-SYSVG.13 K66P144-SYSVG.14 K66P144-SYSVG.15 K66P144-SYSVG.16 K66P144-SYSVG.17 K66P144-SYSVG.18 K66P144-SYSVG.19 K66P144-SYSVG.20 K66P144-SYSVG.21 K66P144-SYSVG.22 K66P144-SYSVG.23 K66P144-SYSVG.24 K66P144-SYSVG.25 K66P144-SYSVG.26 K66P144-SYSVG.27 K66P144-SYSVG.28 K66P144-SYSVG.29 K66P144-SYSVG.30 K66P144-SYSVG.31 K66P144-SYSVG.32 K66P144-SYSVG.33 K66P144-SYSVG.34 K66P144-SYSVG.35 K66P144-SYSVG.36 K66P144-SYSVG.37 K66P144-SYSVG.38 K66P144-SYSVG.39 K66P144-SYSVG.40 K66P144-SYSVG.42 K66P144-SYSVG.44 K66P144-SYSVG.46 K66P144-SYSVG.47 K66P144-SYSVG.48 K66P144-SYSVG.49 K66P144-SYSVG.50 K66P144-SYSVG.51 K66P144-SYSVG.52 K66P144-SYSVG.53 K66P144-SYSVG.54 K66P144-SYSVG.57 K66P144-SYSVG.58 K66P144-SYSVG.59 K66P144-SYSVG.60 K66P144-SYSVG.61 K66P144-SYSVG.62 K66P144-SYSVG.63 K66P144-SYSVG.64 K66P144-SYSVG.65 K66P144-SYSVG.66 K66P144-SYSVG.67 K66P144-SYSVG.68 K66P144-SYSVG.69 K66P144-SYSVG.71 K66P144-SYSVG.72 K66P144-SYSVG.77 K66P144-SYSVG.78 K66P144-SYSVG.79 K66P144-SYSVG.80 K66P144-SYSVG.81 K66P144-SYSVG.82 K66P144-SYSVG.87 K66P144-SYSVG.90 K66P144-SYSVG.93 K66P144-SYSVG.95 K66P144-SYSVG.96 K66P144-SYSVG.97 K66P144-SYSVG.98 K66P144-SYSVG.99 K66P144-SYSVG.100 K66P144-SYSVG.101 K66P144-SYSVG.102 K66P144-SYSVG.103 K66P144-SYSVG.104 K66P144-SYSVG.105 K66P144-SYSVG.106 K66P144-SYSVG.107 K66P144-SYSVG.108 K66P144-SYSVG.119 K66P144-SYSVG.122 S1.3
copper on no net:
  other v2: 2475,3000 6025,3000 6025,5425 2450,5450

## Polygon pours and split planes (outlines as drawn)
GND on Top Layer "Top Layer-No Net" (hatched 90Degree grid 20 track 8, pour order 4): 2400,3283 2668,3015 3200,3015 3281,2934 4652,2934 4692,2894 5407,2894 5644,3131 5834,3131 6012,3309 6081,3309 6091,3319 6091,4035 5984,4142 5779,4142 5694,4227 5694,4427 5782,4515 5967,4515 6075,4623 6075,5136 5995,5216 5836,5216 5643,5409 2559,5409 2465,5315 2465,4596 2530,4531 2530,3820 2368,3658 2368,3306 2373,3306 2402,3277

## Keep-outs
Keep-Out Layer:
  the board outline again, w10

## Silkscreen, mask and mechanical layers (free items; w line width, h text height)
Top Overlay:
  text "GND" at 2655.63,5382.44 h50
  text "SCl" at 2775.63,5382.44 h50
  text "SDA" at 2865.63,5382.44 h50
  text "GND" at 2960.63,5382.44 h50
  text "3.3V" at 3065.63,5382.44 h50
  text "B0" at 4045.63,5352.44 h50
  text "GND" at 4130.63,5352.44 h50
  text "5V" at 4250.63,5352.44 h50
  text "GND" at 4475.63,5312.44 h50
  text "5V" at 4600.63,5312.44 h50
  text "B7" at 4700.63,5312.44 h50
  text "B6" at 4795.63,5312.44 h50
  text "B5" at 4900.63,5312.44 h50
  text "B4" at 5000.63,5312.44 h50
  text "5V" at 5220.63,5307.44 h50
  text "D10" at 5315.63,5307.44 h50
  text "GND" at 5405.63,5307.44 h50
  text "3.3V" at 3295.63,5292.44 h50
  text "CS" at 3405.63,5292.44 h50
  text "D0" at 3500.63,5292.44 h50
  text "GND" at 3590.63,5292.44 h50
  text "CLK" at 3690.63,5292.44 h50
  text "DI" at 3810.63,5292.44 h50
  text "D1" at 2915.63,4520.44 h50 r270
  text "D0" at 2705.63,4480.44 h50 r90
  text "5V" at 5274.63,4437.44 h50
  text "GND" at 5359.63,4437.44 h50
  text "D3" at 2915.63,4420.44 h50 r270
  text "D5" at 2915.63,4320.44 h50 r270
  text "D7" at 2915.63,4220.44 h50 r270
  text "D6" at 2705.63,4180.44 h50 r90
  text "SCL" at 2915.63,4135.44 h50 r270
  text "SDA" at 2705.63,4070.44 h50 r90
  text "HRF" at 2915.63,4035.44 h50 r270
  text "PCK" at 2705.63,3975.44 h50 r90
  text "D15" at 2915.63,3920.44 h50 r270
  text "GND" at 2705.63,3860.44 h50 r90
  text "GND" at 2915.63,3840.44 h50 r270
  text "3.3V" at 2705.63,3770.44 h50 r90
  text "A12" at 4000.63,3272.44 h50
  text "GND" at 4090.63,3272.44 h50
  text "B18" at 2790.63,3267.44 h50
  text "GND" at 2880.63,3267.44 h50
  text "A13" at 4000.63,3032.44 h50
  text "3.3V" at 4095.63,3032.44 h50
  text "B19" at 2780.63,3027.44 h50
  text "3.3V" at 2890.63,3027.44 h50
  text "_" at 5056.26,2971.81 h78.74
  text "+" at 4861.26,2936.81 h78.74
